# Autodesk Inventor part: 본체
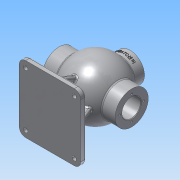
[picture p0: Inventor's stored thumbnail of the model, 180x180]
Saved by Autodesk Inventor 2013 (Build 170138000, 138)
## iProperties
Created: 2018-06
Part Number: 본체
Material: 알루미늄 6061
Document SubType Name: Modeling
Designer: Administrator
Density: 2.71 g/cm^3
Mass: 1509.58 g
Surface Area: 1153.7 cm^2
Volume: 557.041 cm^3
Author: Administrator
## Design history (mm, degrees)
sketch "스케치1"
  geometry: L1 (-68, 0)-(68, 0); L2 (-68, 0)-(-68, 31); L3 (68, 31)-(68, 0); L4 (-68, 31)-(-42.988, 31); L5 (42.988, 31)-(68, 31); A1 r 53 centre (0, 0) between (42.988, 31) and (-42.988, 31); 2 further points
  constraints: 10 end point, 5 perpendicular, 2 coincident, 2 point on circle, 1 centre point, 1 collinear, 1 horizontal, 1 midpoint
  dimensions: "d0" = 106 diameter of A1; "d1" = 136 distance of L1.start L1.end; "d2" = 31 distance of L1.start L2.end
revolve "회전1" sketch "스케치1" stored, may be unused: angle "d3" = 90 deg
sketch "스케치2"
  geometry: L1 (-68, -31)-(-68, 31) reference; L2 (-68, 31)-(-42.988, 31) reference; L3 (42.988, 31)-(68, 31) reference; L4 (68, 31)-(68, -31) reference; L5 (68, -31)-(42.988, -31) reference; L6 (-42.988, -31)-(-68, -31) reference; L7 (-68, 0)-(68, 0); L8 (-68, 0)-(-68, 17.5); L9 (68, 17.5)-(68, 0); L10 (-68, 17.5)-(-39.278, 17.5); L11 (39.278, 17.5)-(68, 17.5); L12 (-52, 18.5)-(-50.25, 18.5); L13 (-50.25, 18.5)-(-50.25, 0); L14 (-50.25, 0)-(-52, 0); L15 (-52, 0)-(-52, 18.5); L16 (-52, 18.5)-(-50.25, 0); L17 (-50.25, 18.5)-(-52, 0); A1 r 43 centre (0, 0) between (39.278, 17.5) and (-39.278, 17.5); A2 r 53 centre (0, 0) between (42.988, 31) and (-42.988, 31) reference; A3 r 53 centre (0, 0) between (-42.988, -31) and (42.988, -31) reference; 4 further points
  constraints: 22 end point, 6 midpoint, 4 perpendicular, 2 parallel, 2 point on circle, 2 point on line, 1 centre point, 1 coincident, 1 collinear, 1 horizontal, 1 horizontal alignment
  dimensions: "d4" = 86 diameter of A1; "d5" = 17.5 distance of L7.start L8.end; "d18" = 1.75 distance of L13.end L14.end; "d19" = 18.5 distance of L12.end L13.end; "d20" = 16 distance between parallel lines of L8 L15
revolve "회전2" sketch "스케치2" stored, may be unused: angle "d6" = 90 deg
sketch "스케치3"
  geometry: L1 (0, 0)-(0, 22.5); C1 r 31 at (0, 0) reference; 1 further point
  constraints: 2 end point, 1 coincident, 1 vertical
  dimensions: "d7" = 22.5 distance of L1.start L1.end
hole "구멍1" sketch "스케치3" at (0, 22.5) diameter "d8" = 3.242; stored, may be unused: countersink angle "d12" = 90 deg, drill point angle "d14" = 118 deg; dims "d9" = 12, "d10" = 4, "d11" = 2, "d13" = 15
sketch "스케치4"
  geometry: L1 (0, 0)-(0, 24); C1 r 31 at (0, 0) reference; 1 further point
  constraints: 2 end point, 1 coincident, 1 vertical
  dimensions: "d21" = 24 distance of L1.start L1.end
hole "구멍2" sketch "스케치4" at (0, 24) diameter "d22" = 3.242; stored, may be unused: countersink angle "d26" = 90 deg, drill point angle "d28" = 118 deg; dims "d23" = 16, "d24" = 4, "d25" = 2, "d27" = 19
node "작업 평면1"
sketch "스케치5"
  geometry: L1 (-57.5, 62.5)-(57.5, 62.5); L2 (57.5, 62.5)-(57.5, -62.5); L3 (57.5, -62.5)-(-57.5, -62.5); L4 (-57.5, -62.5)-(-57.5, 62.5); L5 (-57.5, 62.5)-(57.5, -62.5); L6 (57.5, 62.5)-(-57.5, -62.5); 1 further point
  constraints: 12 end point, 2 midpoint, 2 parallel, 1 horizontal, 1 perpendicular
  dimensions: "d33" = 115 distance of L2.end L3.end; "d34" = 125 distance of L1.end L2.end
extrude "돌출1" join sketch "스케치5" distance "d35" = 10; taper "d36" = 0 deg
sketch "스케치7"
  geometry: L1 (57.5, 62.5)-(-57.5, 62.5) reference; L2 (-4, -52.5)-(4, -52.5); L3 (4, -52.5)-(4, 52.5); L4 (4, 52.5)-(-4, 52.5); L5 (-4, 52.5)-(-4, -52.5); L6 (-4, -52.5)-(4, 52.5); L7 (4, -52.5)-(-4, 52.5); 1 further point
  constraints: 12 end point, 2 midpoint, 2 parallel, 1 horizontal, 1 perpendicular
  dimensions: "d37" = 8 distance of L4.end L3.end; "d38" = 10 distance between parallel lines of L1 L4
extrude "돌출2" join sketch "스케치7" stored distance "d39" = 10; taper "d40" = 0 deg
feature "면 기울기1" dims angle "d41" = 22 deg
sketch "스케치8"
  geometry: L1 (57.5, -62.5)-(57.5, 62.5) reference; L2 (-47.5, 4)-(47.5, 4); L3 (47.5, 4)-(47.5, -4); L4 (47.5, -4)-(-47.5, -4); L5 (-47.5, -4)-(-47.5, 4); L6 (-47.5, 4)-(47.5, -4); L7 (47.5, 4)-(-47.5, -4); 1 further point
  constraints: 12 end point, 2 midpoint, 2 parallel, 1 horizontal, 1 perpendicular
  dimensions: "d42" = 8 distance of L2.end L3.end; "d43" = 10 distance between parallel lines of L1 L3
extrude "돌출3" join sketch "스케치8" stored distance "d44" = 10; taper "d45" = 0 deg
feature "면 기울기2" dims angle "d46" = 22 deg
node "작업 평면2"
sketch "스케치9"
  geometry: C1 r 27 at (0, 0); 1 further point
  constraints: 1 centre point, 1 coincident
  dimensions: "d48" = 54 diameter of C1
extrude "돌출4" join sketch "스케치9" stored distance "d49" = 10; taper "d50" = 0 deg
hole "구멍3" diameter "d53" = 26; stored, may be unused: countersink angle "d57" = 90 deg, drill point angle "d59" = 0 deg; dims "d51" = 10, "d52" = 10, "d54" = 16, "d55" = 4, "d56" = 2, "d58" = 19
sketch "스케치10"
  geometry: L1 (0, 0)-(0, 20); C1 r 13 at (0, 0) reference; 1 further point
  constraints: 2 coincident, 2 end point, 1 vertical
  dimensions: "d60" = 20 distance of L1.start L1.end
hole "구멍4" sketch "스케치10" at (0, 20) diameter "d61" = 3.242; stored, may be unused: countersink angle "d65" = 90 deg, drill point angle "d67" = 118 deg; dims "d62" = 9, "d63" = 4, "d64" = 2, "d66" = 11
fillet "모깎기1" dims "d71" = 12
hole "구멍5" diameter "d74" = 8; stored, may be unused: countersink angle "d78" = 90 deg, drill point angle "d80" = 0 deg; dims "d72" = 10, "d73" = 10, "d75" = 9, "d76" = 12, "d77" = 3, "d79" = 11
chamfer "모따기1" distance "d81" = 1; stored, may be unused: second distance "d82" = 2, angle "d83" = 45 deg
fillet "모깎기2" dims "d84" = 3
fillet "모깎기3" dims "d85" = 3
fillet "모깎기4" dims "d86" = 3
fillet "모깎기5" dims "d87" = 3
node "작업 평면3"
sketch "스케치11"
  geometry: L1 (-50.954, -78)-(-48.622, -78) reference; L2 (-48.622, -78)-(-48.622, -85) reference; L3 (-48.622, -85)-(-57.237, -85) reference; L4 (-57.237, -85)-(-57.237, -78) reference; L5 (-54.146, -75)-(-50.954, -75) reference; L6 (-50.954, -75)-(-50.954, -78) reference; L7 (40.046, -78)-(42.378, -78) reference; L8 (42.378, -78)-(42.378, -85) reference; L9 (42.378, -85)-(-42.378, -85) reference; L10 (-42.378, -85)-(-42.378, -78) reference; L11 (-42.378, -78)-(-40.046, -78) reference; L12 (-40.046, -78)-(-40.046, -75) reference; L13 (-40.046, -75)-(-4.867, -75) reference; L14 (-1, -74.584)-(1, -74.584) reference; L15 (4.867, -75)-(40.046, -75) reference; L16 (40.046, -75)-(40.046, -78) reference; L17 (48.622, -78)-(50.954, -78) reference; L18 (50.954, -78)-(50.954, -75) reference; L19 (50.954, -75)-(54.146, -75) reference; L20 (57.237, -78)-(57.237, -85) reference; L21 (57.237, -85)-(48.622, -85) reference; L22 (48.622, -85)-(48.622, -78) reference; L23 (-27, 65)-(27, 65) reference; 3 further points
  constraints: 1 vertical alignment, 5 other
  dimensions: "d88" = 10 distance from line of L23 point (0, 55)
feature "엠보싱1" sketch "스케치11" dims "d0" = 106, "d1" = 136, "d2" = 31, "d89" = 0.5, "d90" = 0
node "솔리드1"
pattern_circular "원형 패턴1" dims angle "d16" = 360 deg
pattern_circular "원형 패턴2" dims angle "d30" = 360 deg
pattern_circular "원형 패턴3" dims angle "d69" = 360 deg
mirror "대칭1"
mirror "대칭2"
node "절단 모서리 투영1"
node "절단 모서리 투영2"
other parameters: "d32" = -85
